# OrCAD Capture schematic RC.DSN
size A
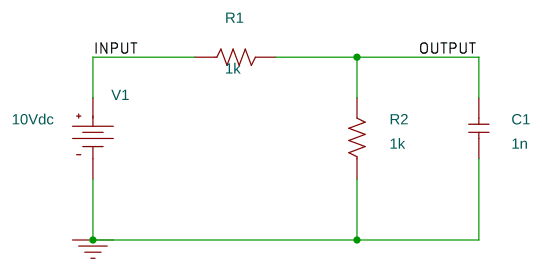
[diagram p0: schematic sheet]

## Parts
C1  1n  [CK05]
R1  1k  [RC05]
R2  1k  [RC05]
V1  VDC

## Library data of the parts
C1 = C
R1 R2 = R
V1 = VDC: DC: 10Vdc

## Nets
0: C1.1 R2.1 V1.1(-)
INPUT : R1.1 V1.0(+)
OUTPUT: C1.2 R1.2 R2.2
